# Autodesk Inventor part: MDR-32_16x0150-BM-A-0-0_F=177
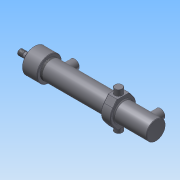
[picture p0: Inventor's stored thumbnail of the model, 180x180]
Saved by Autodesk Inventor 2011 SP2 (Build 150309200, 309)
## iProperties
Created: 2015-10
Part Number: MDR-32_16x0150-BM-A-0-0_F=177
Material: Сталь
Document SubType Name: Modeling
Designer: Дорохин
Mass: 17664.9 g
Surface Area: 1563.91 cm^2
Volume: 2250.3 cm^3
Density: 7.85 g/cm^3
Author: Дорохин
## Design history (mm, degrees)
sketch "Эскиз1"
  geometry: L1 (0, 0)-(0, 5.25); L2 (0, 5.25)-(0.75, 6); L3 (0.75, 6)-(10, 6); L4 (10, 6)-(10.75, 5.25); L5 (10.75, 5.25)-(16, 5.25); L6 (16, 5.25)-(16, 6); L7 (16, 6)-(17, 7); L8 (17, 7)-(21, 7); L9 (21, 7)-(22, 8); L10 (22, 8)-(30, 8); L11 (30, 8)-(30, 25); L12 (31, 26)-(61, 26); L13 (219, 20)-(285, 20); L14 (286, 19)-(286, 0); L15 (286, 0)-(0, 0); L16 (286, 19)-(285, 20); L17 (62, 25)-(62, 20); L18 (217, 22)-(217, 27); L19 (217, 27)-(197, 27); L20 (197, 27)-(197, 22); L21 (195, 20)-(62, 20); L22 (31, 26)-(30, 25); L23 (61, 26)-(62, 25); L24 (197, 22)-(195, 20); L25 (217, 22)-(219, 20); 5 further points
  constraints: 50 end point, 10 point on line, 8 perpendicular, 6 parallel, 2 vertical
  dimensions: "d0" = 16 distance between parallel lines of L6 L1; "d1" = 30 distance between parallel lines of L1 L11; "d6" = 256 distance between parallel lines of L14 L11; "d10" = 40 diameter of L13 L15; "d19" = 52 diameter of L12 L15; "d20" = 16 diameter of L10 L15; "d21" = 45 deg angle of L10 L9; "d22" = 14 diameter of L8 L15; "d23" = 12 diameter of L6.end L15 (computed from d22); "d26" = 5 distance from line of L8.end L6; "d27" = 12 diameter of L3 L15; "d28" = 45 deg angle of L3 L2; "d29" = 10.5 diameter of L1.end L15; "d32" = 6 distance from line of L6 L3.end; "d34" = 1 distance of L14.start point (286, 20); "d35" = 1 distance of L13.end point (286, 20) (= d34); "d91" = 40 diameter of L21 L15; "d92" = 54 diameter of L19 L15; "d93" = 45 deg angle of L3 L4; "d94" = 10.5 diameter of L5 L15; "d95" = 45 deg angle of L8 L7 (derived); "d96" = 32 distance between parallel lines of L17 L11; "d97" = 20 distance between parallel lines of L20 L18; "d98" = 167 distance between parallel lines of L20 L11; "d105" = 1 distance of L12.start point (30, 26); "d106" = 1 distance of L11.end point (30, 26) (= d105); "d107" = 1 distance of L12.end point (62, 26) (= d105); "d108" = 1 distance of L17.start point (62, 26) (= d107); "d113" = 2 distance of L20.end point (197, 20); "d114" = 2 distance of L21.start point (197, 20) (= d113); "d115" = 2 distance of L18.start point (217, 20) (= d113); "d116" = 2 distance of L13.start point (217, 20) (= d115)
revolve "Вращение1" sketch "Эскиз1" stored, may be unused: angle "d33" = 90 deg
sketch "Эскиз2"
  geometry: L1 (-286, 19)-(-286, -19) reference; L2 (-30, 25)-(-30, -25) reference; C1 r 10 at (-80, 0); C2 r 10 at (-260, 0); 1 further point
  constraints: 2 centre point
  dimensions: "d36" = 20 diameter of C1 (= d37); "d37" = 20 diameter of C2; "d38" = 0 vertical distance of C2.centre C1.centre; "d39" = 0 vertical distance of C1.centre point (0, 0); "d43" = 26 distance from line of L1 C2.centre; "d117" = 50 distance from line of C1.centre L2
extrude "Выдавливание1" join sketch "Эскиз2" distance "d44" = 35; taper "d45" = 0 deg
hole "Отверстие1" diameter "d48" = 11.445; stored, may be unused: countersink angle "d52" = 90 deg, drill point angle "d54" = 0 deg; dims "d46" = 10, "d47" = 10, "d49" = 15, "d50" = 13.5, "d51" = 2, "d53" = 19
hole "Отверстие2" diameter "d57" = 11.445; stored, may be unused: countersink angle "d61" = 90 deg, drill point angle "d63" = 0 deg; dims "d55" = 10, "d56" = 10, "d58" = 15, "d59" = 13.5, "d60" = 2, "d62" = 19
chamfer "Фаска1" distance "d64" = 0.5; stored, may be unused: second distance "d65" = 2, angle "d66" = 45 deg
feature "Резьба1" dims "d79" = 10, "d80" = 0
sketch "Эскиз4"
  geometry: L1 (16, -6)-(16, 6) reference; C1 r 1 at (18.5, 0); 1 further point
  constraints: 1 centre point
  dimensions: "d83" = 2 diameter of C1; "d84" = 0 vertical distance of C1.centre point (0, 0); "d85" = 2.5 distance from line of L1 C1.centre
extrude "Выдавливание2" cut sketch "Эскиз4" stored distance "d86" = 90; taper "d87" = 0 deg
feature "Резьба3" dims "d118" = 5, "d119" = 128
node "РабПлоскость1"
sketch "Эскиз6"
  geometry: L1 (-40, 0)-(40, 0); L2 (40, 0)-(40, 7.5); L3 (39.5, 8)-(-39.5, 8); L4 (-40, 7.5)-(-40, 0); L5 (-40, 7.5)-(-39.5, 8); L6 (39.5, 8)-(40, 7.5); 3 further points
  constraints: 12 end point, 4 point on line, 2 parallel, 1 horizontal, 1 midpoint, 1 perpendicular
  dimensions: "d130" = 16 diameter of L3 L1; "d131" = 40 distance from line of point (0, 0) L4 (= 0.5 x d132); "d132" = 80 distance between parallel lines of L2 L4; "d133" = 0.5 distance of L4.start point (-40, 8); "d134" = 0.5 distance of L3.end point (-40, 8) (= d133); "d135" = 0.5 distance of L3.start point (40, 8) (= d133); "d136" = 0.5 distance of L2.end point (40, 8) (= d135)
revolve "Вращение3" sketch "Эскиз6" stored, may be unused: angle "d137" = 90 deg
sketch "Эскиз7"
  geometry: L1 (-16.492, 21.378)-(-28, 12.5); L2 (-28, 12.5)-(-28, -12.5); L3 (-28, -12.5)-(-16.492, -21.378); L4 (16.492, -21.378)-(28, -12.5); L5 (28, -12.5)-(28, 12.5); L6 (28, 12.5)-(16.492, 21.378); L7 (0, 0)-(11.51, 0); A1 r 27 centre (0, 0) between (-16.492, 21.378) and (-16.492, -21.378) reference; A2 r 27 centre (0, 0) between (-16.492, 21.378) and (-16.492, -21.378) reference
  constraints: 14 end point, 8 point on circle, 4 tangent, 1 parallel, 1 perpendicular, 1 vertical
  dimensions: "d138" = 56 distance between parallel lines of L5 L2; "d139" = 28 distance from line of A1.centre L2 (= 0.5 x d138); "d140" = 25 distance of L1.end L2.end; "d141" = 25 distance of L4.end L5.end (= d140); "d142" = 12.5 vertical distance of L1.end A1.centre (= 0.5 x d140); "d143" = 0 vertical distance of L5.end L1.end
extrude "Выдавливание3" join sketch "Эскиз7" distance "d145" = 20; taper "d146" = 0 deg
chamfer "Фаска2" distance "d147" = 1; stored, may be unused: second distance "d148" = 2, angle "d149" = 45 deg
sketch "Эскиз8"
  geometry: L1 (276, 16)-(261, 16); L2 (261, 16)-(261, 8); L3 (261, 8)-(276, 8); L4 (276, 8)-(276, 16); L5 (231, 16)-(81, 16); L6 (81, 16)-(81, 8); L7 (81, 8)-(231, 8); L8 (231, 8)-(231, 16); L9 (286, -19)-(286, 19) reference; L10 (286, 0)-(0, 0); L11 (0, -5.25)-(0, 5.25) reference
  constraints: 18 end point, 4 parallel, 3 perpendicular, 2 horizontal, 1 midpoint
  dimensions: "d150" = 16 diameter of L3 L10; "d151" = 16 diameter of L7 L10; "d152" = 32 diameter of L5 L10; "d154" = 32 diameter of L1 L10; "d155" = 10 distance between parallel lines of L4 L9; "d156" = 15 distance between parallel lines of L4 L2; "d157" = 30 distance between parallel lines of L8 L2; "d158" = 150 distance of L6.end L7.end
revolve "Вращение4" sketch "Эскиз8" stored, may be unused: angle "d159" = 90 deg
node "Твердое тело1"
